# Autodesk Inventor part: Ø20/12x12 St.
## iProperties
Company: Mayer & Müller Schaltgeräte
Created: 2005-06
Part Number: Ø20/12x12 St.
Material: 1.0718
Document SubType Name: Modeling
Designer: I.Baliuc
Manufacturer: Standard
Standards Organization: Custom
Description: Einpressbuchse
Density: 7.86 g/cm^3
Author: T.Messerschmitt
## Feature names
1. Drehung1 [Revolution]
